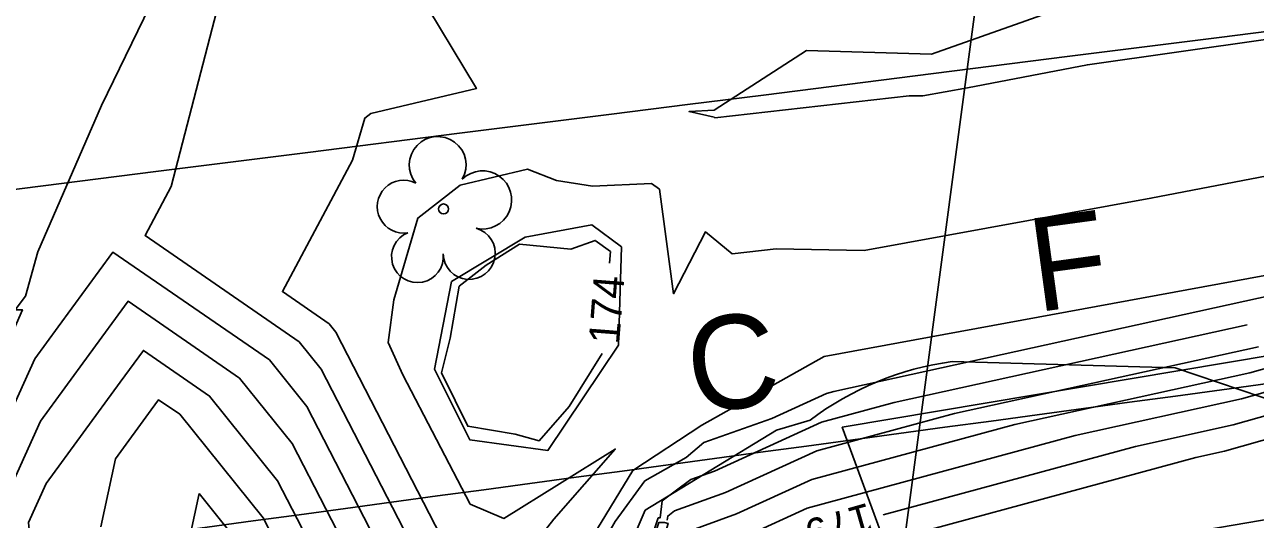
# Model space of a CAD drawing. Extents: x 2086416 to 2115205, y 575507 to 632762.
# Drawn here: x 2112066 to 2112146.4, y 581757.5 to 581789.8 of the extents above; entities that cross this region are included whole.
import ezdxf

# ---------------------------------------------------------------- set-up
doc = ezdxf.new("R2010")
doc.units = 0
for name, color, linetype in [('DTM Contours Major', 7, 'Continuous'), ('DTM Contours Minor', 7, 'Continuous'), ('DTM Contours Minor Text', 7, 'Continuous'), ('Exist Hydro Stream or Body of Water', 7, 'Continuous'), ('Exist Hydrographic FEMA Cross Section', 7, 'Continuous'), ('Exist Right of Way Line', 7, 'Continuous'), ('Exist Vegetation Tree CELL', 7, 'Continuous'), ('Exist Vegetation Woods Line', 7, 'Continuous'), ('Prop Horizontal Alignment Station Label', 7, 'Continuous'), ('Prop SS Cut Line', 7, 'Continuous'), ('Prop SS Cut Text', 7, 'Continuous'), ('Prop SS Fill Line', 7, 'Continuous'), ('Prop SS Fill Text', 7, 'Continuous')]:
    doc.layers.add(name, color=color, linetype=linetype)

# ---------------------------------------------------------------- blocks, each defined once
blk = doc.blocks.new('EXIST VEGETATION TREE')
at = {"layer": 'Exist Vegetation Tree CELL'}
blk.add_line((0, 0), (0, 0), dxfattribs=at)
blk.add_circle((0, 0), 0.00652, dxfattribs=at)
for centre, radius, start, end in [((-0.0077, 0.0575), 0.0371, 330.1651, 219.7134), ((0.051, 0.0118), 0.038, 257.1011, 134.1999), ((-0.0521, 0.0031), 0.0345, 62.6636, 279.3457), ((-0.0341, -0.0624), 0.0338, 111.5671, 6.231), ((0.0335, -0.058), 0.034, 181.2822, 74.56)]:
    blk.add_arc(centre, radius, start, end, dxfattribs=at)

msp = doc.modelspace()

# ---------------------------------------------------------------- linework, layer by layer
at = {"layer": 'DTM Contours Major'}
for points in [[(2112093.804, 581744.757), (2112090.042, 581754.014), (2112084.44, 581764.888), (2112082.003, 581767.922), (2112071.785, 581774.964), (2112068.207, 581770.089), (2112066.687, 581768.005), (2112059.39, 581751.908), (2112059.991, 581745.748), (2112060.467, 581736.615), (2112060.524, 581732.474), (2112061.368, 581723.884), (2112065.2, 581717.945)], [(2112145.839, 581770.21), (2112122.802, 581765.151), (2112118.062, 581763.867), (2112111.066, 581760.66), (2112109.531, 581760.105), (2112107.648, 581758.718), (2112107.517, 581757.603), (2112107.398, 581757.603), (2112105.963, 581753.367)], [(2112107.271, 581718.408), (2112107.011, 581720.415), (2112104.169, 581741.708), (2112103.667, 581744.929), (2112103.375, 581747.122), (2112103.578, 581747.166), (2112103.753, 581747.19), (2112103.841, 581746.714), (2112104.339, 581748.104), (2112105.63, 581751.758), (2112105.895, 581751.758), (2112105.958, 581751.161), (2112105.765, 581750.292), (2112105.481, 581749.341), (2112113.377, 581753.212), (2112114.641, 581753.669), (2112116.475, 581754.51), (2112142.486, 581761.555), (2112144.37, 581761.969), (2112152.892, 581764.375), (2112153.328, 581764.365), (2112159.99, 581765.28), (2112164.963, 581765.862)]]:
    msp.add_lwpolyline(points, dxfattribs=at)
at = {"layer": 'DTM Contours Minor'}
for points in [[(2112088.832, 581814.717), (2112079.117, 581800.733), (2112078.139, 581799.131), (2112071.052, 581784.529), (2112066.895, 581774.978), (2112066.081, 581772.081), (2112065.416, 581771.202), (2112065.876, 581771.198), (2112064.244, 581767.513), (2112055.948, 581749.212), (2112056.111, 581747.536), (2112056.41, 581741.807), (2112056.854, 581736.905), (2112057.524, 581734.784), (2112059.14, 581725.01)], [(2112090.867, 581814.656), (2112090.381, 581813.617), (2112080.779, 581799.37), (2112080.326, 581797.56), (2112075.592, 581779.241), (2112073.887, 581776.041), (2112083.954, 581769.103), (2112085.39, 581767.315), (2112092.199, 581754.098), (2112096.773, 581742.846), (2112096.783, 581742.376), (2112097.229, 581741.374), (2112099.723, 581728.458), (2112099.682, 581727.468)], [(2112153.005, 581789.685), (2112135.416, 581787.2), (2112127.574, 581785.689), (2112124.665, 581785.159), (2112123.771, 581785.177), (2112111.094, 581783.733), (2112111.035, 581783.781), (2112109.405, 581784.144), (2112111.049, 581784.24), (2112117.074, 581788.124), (2112125.244, 581787.878), (2112134.648, 581791.209), (2112153.514, 581797.044), (2112157.376, 581796.211), (2112168.643, 581796.696), (2112174.716, 581797.127), (2112198.243, 581802.384), (2112199.855, 581802.612), (2112215.462, 581799.046), (2112243.201, 581806.994), (2112245.026, 581807.254), (2112246.641, 581807.449), (2112260.422, 581806.872)], [(2112091.592, 581792.199), (2112095.525, 581785.642), (2112088.629, 581784.023), (2112088.241, 581783.718), (2112087.421, 581780.959), (2112082.853, 581772.387), (2112085.905, 581770.284), (2112086.341, 581769.742), (2112094.357, 581754.182), (2112095.8, 581750.633), (2112098.322, 581744.525), (2112099.495, 581740.557), (2112101.403, 581730.014), (2112101.767, 581728.727), (2112101.91, 581726.997), (2112102.26, 581718.435), (2112100.298, 581715.176), (2112100.199, 581713.005), (2112098.939, 581705.624), (2112099.971, 581703.175), (2112100.091, 581700.325), (2112099.464, 581694.624)], [(2112277.586, 581789.768), (2112248.197, 581785.998), (2112247.037, 581785.904), (2112231.348, 581784.073), (2112223.26, 581783.128), (2112217.816, 581784.761), (2112201.188, 581783.128), (2112192.056, 581780.852), (2112182.632, 581778.883), (2112164.02, 581774.995), (2112153.603, 581773.464), (2112153.187, 581773.415), (2112147.809, 581772.235), (2112147.676, 581772.198), (2112118.865, 581765.87), (2112118.38, 581765.739), (2112114.812, 581764.103), (2112110.366, 581762.541), (2112109.222, 581761.56), (2112106.527, 581760.029), (2112104.587, 581757.383), (2112103.763, 581755.943), (2112103.404, 581754.716)], [(2112307.142, 581785.738), (2112301.4, 581785.104), (2112285.905, 581782.951), (2112280.275, 581782.232), (2112257.984, 581779.142), (2112250.535, 581778.186), (2112235.839, 581776.992), (2112231.218, 581776.453), (2112221.989, 581775.375), (2112201.465, 581773.622), (2112194.785, 581772.636), (2112183.064, 581771.258), (2112173.059, 581769.787), (2112153.283, 581767.472), (2112151.503, 581767.081), (2112145.472, 581765.379), (2112134.612, 581762.993), (2112117.11, 581758.253), (2112113.211, 581756.465), (2112110.524, 581755.494), (2112110.041, 581755.257)], [(2112319.856, 581781.597), (2112316.737, 581781.967), (2112303.887, 581783.453), (2112301.358, 581783.173), (2112281.8, 581780.456), (2112280.881, 581780.338), (2112253.083, 581776.485), (2112251.12, 581776.233), (2112233.04, 581774.765), (2112231.186, 581774.548), (2112227.483, 581774.116), (2112201.413, 581771.889), (2112197.868, 581771.366), (2112183.101, 581769.629), (2112177.923, 581768.868), (2112153.307, 581765.986), (2112152.426, 581765.792), (2112144.921, 581763.674), (2112138.549, 581762.274), (2112122.072, 581757.811)], [(2112149.875, 581780.468), (2112139.56, 581778.479), (2112120.846, 581775.075), (2112115.093, 581775.188), (2112112.213, 581774.86), (2112110.474, 581776.28), (2112108.396, 581772.246), (2112107.475, 581779.066), (2112106.96, 581779.439), (2112103.094, 581779.264), (2112100.758, 581779.64), (2112098.862, 581780.377), (2112094.461, 581779.344), (2112091.702, 581777.181), (2112090.119, 581771.853), (2112089.765, 581769.064), (2112090.723, 581766.943), (2112095.114, 581758.513), (2112097.309, 581757.571), (2112104.588, 581762.098), (2112100.566, 581757.534), (2112098.766, 581755.217)], [(2112094.139, 581765.264), (2112093.237, 581767.084), (2112093.799, 581769.345), (2112094.397, 581772.731), (2112096.147, 581774.115), (2112098.345, 581775.482), (2112101.694, 581775.147), (2112103.279, 581775.728), (2112104.285, 581774.995), (2112104.203, 581774.24)], [(2112090.836, 581746.669), (2112087.884, 581753.931), (2112083.489, 581762.461), (2112080.052, 581766.74), (2112072.781, 581771.751), (2112070.235, 581768.282), (2112067.06, 581763.928), (2112062.833, 581754.603), (2112063.87, 581743.961), (2112064.236, 581736.951), (2112064.376, 581726.748), (2112064.675, 581723.707), (2112066.115, 581721.476), (2112068.073, 581718.32), (2112071.422, 581714.164), (2112071.682, 581713.878)], [(2112087.867, 581748.58), (2112085.726, 581753.847), (2112082.539, 581760.034), (2112078.101, 581765.559), (2112073.777, 581768.539), (2112072.264, 581766.476), (2112067.433, 581759.852), (2112066.276, 581757.299), (2112067.75, 581742.174), (2112068.005, 581737.287), (2112068.16, 581725.983), (2112068.216, 581725.303)], [(2112103.742, 581768.336), (2112101.571, 581764.883), (2112099.629, 581762.644), (2112098.042, 581763.072), (2112094.957, 581763.592), (2112094.139, 581765.264)], [(2112150.579, 581768.369), (2112146.023, 581767.083), (2112130.675, 581763.713), (2112117.427, 581760.124), (2112112.496, 581757.864), (2112109.098, 581756.635), (2112107.635, 581755.918), (2112108.031, 581757.245), (2112107.795, 581757.314), (2112107.436, 581757.313), (2112107.058, 581756.199), (2112104.989, 581750.342), (2112103.82, 581747.082), (2112103.78, 581747.296), (2112103.701, 581747.285), (2112103.231, 581747.183), (2112103.366, 581746.17), (2112104.524, 581738.731), (2112105.941, 581728.117), (2112106.054, 581727.247)], [(2112146.574, 581768.788), (2112126.738, 581764.432), (2112117.745, 581761.996), (2112111.781, 581759.262), (2112108.464, 581758.062), (2112108.01, 581757.728), (2112107.978, 581757.459)], [(2112071.003, 581757.024), (2112071.955, 581761.465), (2112074.292, 581764.67), (2112074.774, 581765.326), (2112076.15, 581764.378), (2112081.589, 581757.607), (2112083.569, 581753.763), (2112084.898, 581750.491), (2112085.142, 581739.573), (2112087.471, 581734.336), (2112088.353, 581726.882), (2112087.997, 581722.183)], [(2112077.754, 581727.498), (2112076.067, 581730.334), (2112075.563, 581736.481), (2112075.543, 581737.96), (2112075.509, 581738.599), (2112075.253, 581741.23), (2112076.507, 581754.952), (2112077.416, 581759.191)], [(2112077.416, 581759.191), (2112080.638, 581755.179), (2112081.411, 581753.68), (2112081.93, 581752.403), (2112082.232, 581738.873), (2112082.847, 581737.489), (2112084.19, 581726.14), (2112084.044, 581724.22), (2112082.798, 581723.839), (2112082.417, 581724.036)]]:
    msp.add_lwpolyline(points, dxfattribs=at)
at = {"layer": 'Exist Hydro Stream or Body of Water'}
for points in [[(2112100.331, 581748.533), (2112103.118, 581756.422), (2112105.733, 581760.694), (2112110.228, 581763.659), (2112118.219, 581768.137), (2112152.909, 581774.525), (2112200.706, 581786.301), (2112247.28, 581789.733), (2112301.109, 581801.74), (2112342.553, 581803.718), (2112346.945, 581801.461), (2112350.791, 581799.078), (2112399.711, 581802.75), (2112440.348, 581810.488), (2112440.68, 581811.969), (2112437.892, 581820.198), (2112440.302, 581822.201), (2112435.858, 581828.249), (2112435.37, 581831.558), (2112437.975, 581841.005), (2112494.538, 581874.355), (2112499.44, 581880.388)], [(2112098.7, 581775.942), (2112103.054, 581776.74), (2112104.994, 581775.3), (2112104.794, 581768.879), (2112100.185, 581762.019), (2112095.093, 581762.7), (2112092.786, 581767.324), (2112093.896, 581773.036), (2112098.7, 581775.942)]]:
    msp.add_lwpolyline(points, dxfattribs=at)
at = {"layer": 'Exist Hydrographic FEMA Cross Section'}
msp.add_lwpolyline([(2112263.01, 581803.998), (2112253.094, 581802.748), (2112243.177, 581801.498), (2112233.261, 581800.243), (2112223.344, 581798.993), (2112213.427, 581797.743), (2112203.511, 581796.488), (2112193.594, 581795.238), (2112183.677, 581793.988), (2112173.76, 581792.732), (2112163.844, 581791.482), (2112153.927, 581790.232), (2112144.01, 581788.977), (2112134.094, 581787.727), (2112124.177, 581786.477), (2112114.26, 581785.222), (2112109.302, 581784.597), (2112104.339, 581783.972), (2112094.422, 581782.722), (2112084.505, 581781.472), (2112074.589, 581780.217), (2112064.672, 581778.967)], dxfattribs=at)
at = {"layer": 'Exist Right of Way Line'}
msp.add_arc((2100483.795, 667614.96), 86637.248, 277.64238767, 277.77100557, dxfattribs=at)
at = {"layer": 'Exist Vegetation Woods Line'}
msp.add_lwpolyline([(2112301.36, 581782.951), (2112202.062, 581766.89), (2112123.133, 581753.422), (2112119.41, 581763.532), (2112200.966, 581777.217), (2112301.435, 581791.882), (2112399.2, 581802.758), (2112436.699, 581809.606), (2112455.709, 581861.801)], dxfattribs=at)
at = {"layer": 'Prop Horizontal Alignment Station Label'}
msp.add_line((2112120.307, 581732.422), (2112135.809, 581848.952), dxfattribs=at)
at = {"layer": 'Prop SS Cut Line'}
for p, q in [((2112115.106, 581763.341), (2112117.304, 581763.989)), ((2112106.542, 581758.12), (2112115.106, 581763.341)), ((2112102.317, 581748.288), (2112106.542, 581758.12))]:
    msp.add_line(p, q, dxfattribs=at)
at = {"layer": 'Prop SS Fill Line'}
for q in [(2112126.579, 581767.813), (2112161.906, 581760.405)]:
    msp.add_line((2112141.145, 581767.399), q, dxfattribs=at)
msp.add_arc((2112129.24, 581748.197), 19.795, 97.72442, 127.08439, dxfattribs=at)

# ---------------------------------------------------------------- block references
at = {"layer": 'Exist Vegetation Tree CELL', "xscale": 50, "yscale": 50}
msp.add_blockref('EXIST VEGETATION TREE', (2112093.376, 581777.779), dxfattribs=at)

# ---------------------------------------------------------------- texts
at = {"layer": 'DTM Contours Minor Text'}
for s, rotation, p in [('174', 85.5338, (2112104.838, 581768.904)), ('179', 195.98907, (2112121.089, 581758.615))]:
    msp.add_text(s, height=2, rotation=rotation, dxfattribs=at).set_placement(p)
at = {"layer": 'Prop SS Cut Text'}
msp.add_text('C', height=6.104, rotation=7.77101, dxfattribs=at).set_placement((2112109.713, 581764.366))
at = {"layer": 'Prop SS Fill Text'}
msp.add_text('F', height=6.104, rotation=7.77101, dxfattribs=at).set_placement((2112132.107, 581771.034))

doc.saveas('drawing.dxf')
